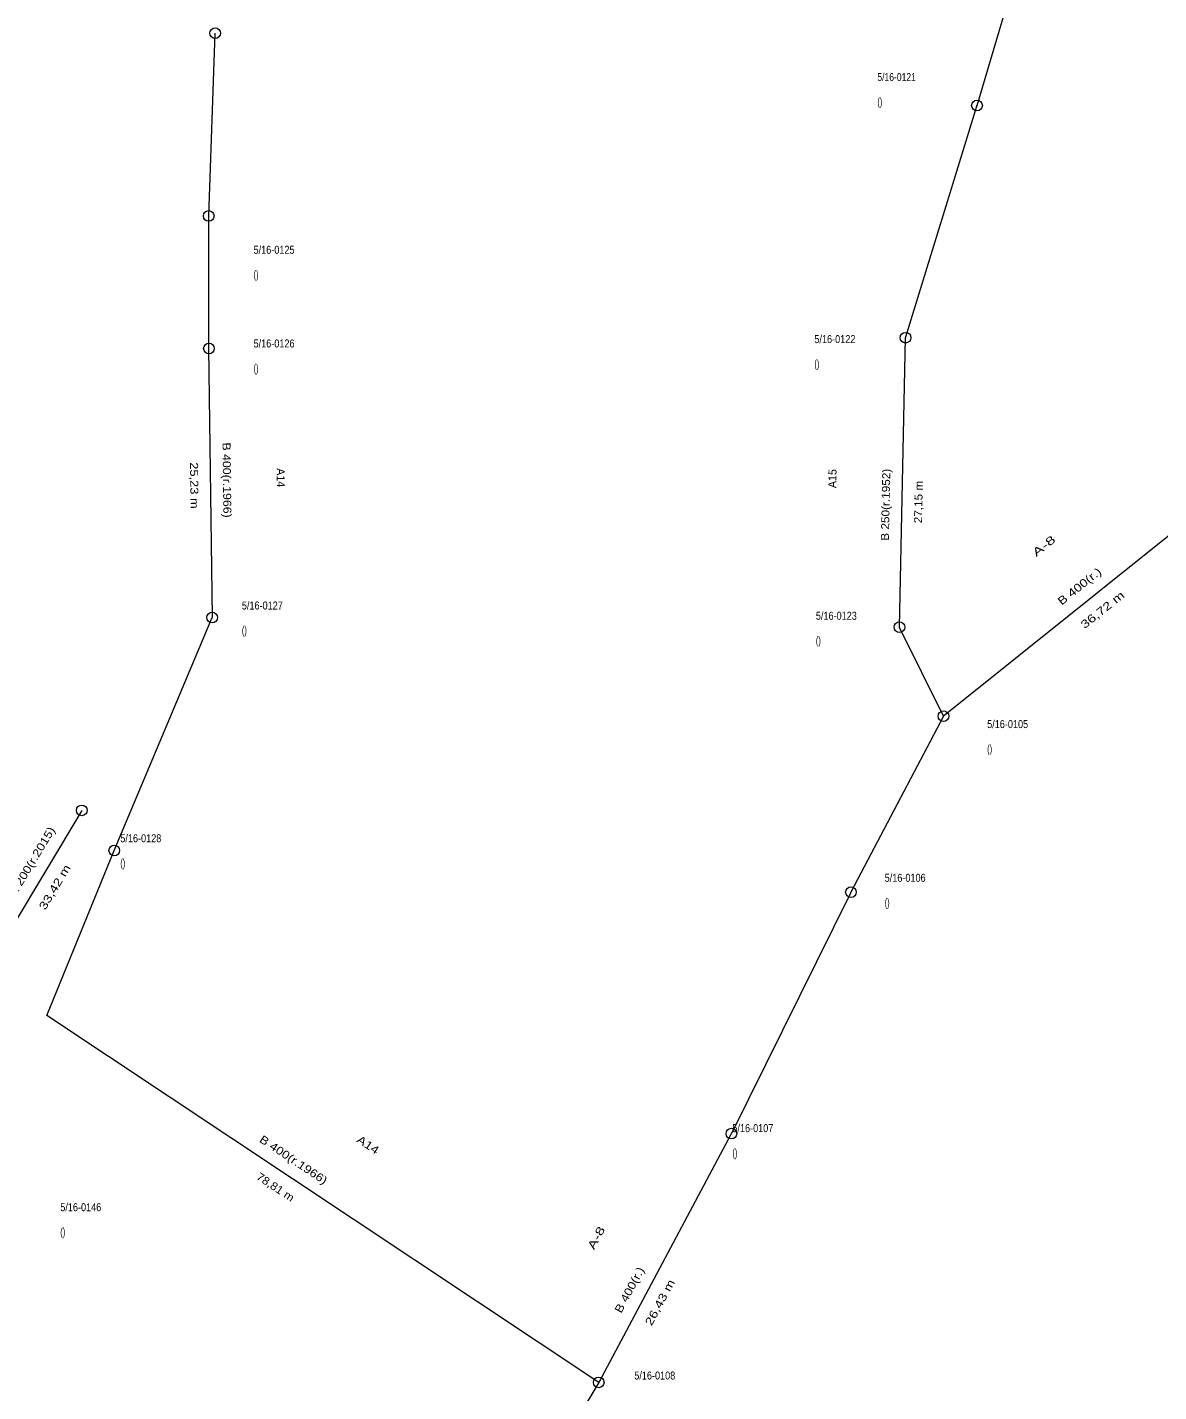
# Model space of a CAD drawing. Extents: x -710854 to -709799, y -1117012 to -1115891.
# Drawn here: x -710384 to -710277.9, y -1116426.2 to -1116298.3 of the extents above; entities that cross this region are included whole.
import ezdxf
from ezdxf.enums import TextEntityAlignment as Align

# ---------------------------------------------------------------- set-up
doc = ezdxf.new("R2010")
doc.units = 0
doc.header["$LTSCALE"] = 0.3
for name, color, linetype, lineweight in [('36', 7, 'Continuous', 13), ('38', 7, 'Continuous', 13), ('44', 7, 'Continuous', 13)]:
    doc.layers.add(name, color=color, linetype=linetype, lineweight=lineweight)
doc.layers.add('48', color=7, linetype='Continuous')

msp = doc.modelspace()

# ---------------------------------------------------------------- linework, layer by layer
at = {"layer": '36'}
msp.add_lwpolyline([(-710378.88, -1116371.72), (-710388.76, -1116388.16), (-710389.13, -1116388.78)], dxfattribs=at)
at = {"layer": '38'}
msp.add_line((-710375.83, -1116375.48), (-710366.654, -1116353.643), dxfattribs=at)
for points in [[(-710294.973, -1116305.64), (-710294.97, -1116305.63), (-710288.78, -1116284.72)], [(-710366.98, -1116315.992), (-710366.98, -1116315.99), (-710366.38, -1116298.86)], [(-710301.668, -1116327.403), (-710301.647, -1116327.335), (-710294.989, -1116305.692), (-710294.973, -1116305.64)], [(-710366.96, -1116328.421), (-710366.96, -1116328.42), (-710366.96, -1116328.387), (-710366.98, -1116315.992)], [(-710302.243, -1116354.545), (-710302.25, -1116354.53), (-710301.67, -1116327.41), (-710301.668, -1116327.403)], [(-710366.654, -1116353.643), (-710366.64, -1116353.61), (-710366.96, -1116328.421)], [(-710269.449, -1116339.945), (-710269.513, -1116339.986), (-710269.55, -1116340.01), (-710298.12, -1116362.88), (-710306.783, -1116379.381)], [(-710298.12, -1116362.88), (-710302.199, -1116354.633), (-710302.243, -1116354.545)], [(-710330.43, -1116425.34), (-710382.14, -1116390.95), (-710375.83, -1116375.48)], [(-710306.783, -1116379.381), (-710306.84, -1116379.49), (-710317.99, -1116402.01), (-710317.995, -1116402.02)], [(-710317.995, -1116402.02), (-710318.009, -1116402.045), (-710330.43, -1116425.34)], [(-710330.43, -1116425.34), (-710338.348, -1116438.576), (-710338.35, -1116438.58), (-710338.376, -1116438.602), (-710356.573, -1116453.802)]]:
    msp.add_lwpolyline(points, dxfattribs=at)
at = {"layer": '44'}
for centre in [(-710366.38, -1116298.86), (-710294.973, -1116305.64), (-710366.98, -1116315.992), (-710301.668, -1116327.403), (-710366.96, -1116328.421), (-710366.654, -1116353.643), (-710302.243, -1116354.545), (-710298.12, -1116362.88), (-710378.88, -1116371.72), (-710375.83, -1116375.48), (-710306.783, -1116379.381), (-710317.995, -1116402.02), (-710330.43, -1116425.34)]:
    msp.add_circle(centre, 0.5, dxfattribs=at)

# ---------------------------------------------------------------- texts
at = {"layer": '48'}
for s, width, p in [('5/16-0121', 0.8, (-710304.313, -1116303.343)), ('()', 0.7, (-710304.313, -1116305.653)), ('5/16-0125', 0.85, (-710362.777, -1116319.537)), ('()', 0.7, (-710362.777, -1116321.847)), ('5/16-0126', 0.85, (-710362.777, -1116328.32)), ('5/16-0122', 0.85, (-710310.214, -1116327.909)), ('()', 0.7, (-710362.777, -1116330.63)), ('()', 0.7, (-710310.214, -1116330.219)), ('5/16-0127', 0.85, (-710363.875, -1116352.886)), ('5/16-0123', 0.85, (-710310.077, -1116353.847)), ('()', 0.7, (-710363.875, -1116355.196)), ('()', 0.7, (-710310.077, -1116356.157)), ('5/16-0105', 0.85, (-710294.02, -1116364.003)), ('()', 0.7, (-710294.02, -1116366.313)), ('5/16-0128', 0.85, (-710375.266, -1116374.707)), ('()', 0.7, (-710375.266, -1116377.017)), ('5/16-0106', 0.85, (-710303.627, -1116378.413)), ('()', 0.7, (-710303.627, -1116380.723)), ('5/16-0107', 0.85, (-710317.9, -1116401.881)), ('()', 0.7, (-710317.9, -1116404.191)), ('5/16-0146', 0.85, (-710380.893, -1116409.292)), ('()', 0.7, (-710380.893, -1116411.602)), ('5/16-0108', 0.85, (-710327.095, -1116425.074))]:
    msp.add_text(s, height=0.75, dxfattribs=dict(at, width=width)).set_placement(p)
for s, rotation, width, p in [('B 400(r.1966)', 270.73, 1.15, (-710365.644, -1116340.7587)), ('25,23 m', 270.73, 1.2, (-710368.7073, -1116341.2637)), ('B 250(r.1952)', 88.77, 1.1, (-710303.1647, -1116343.0695)), ('27,15 m', 88.77, 1.1, (-710300.0887, -1116342.819)), ('A-8', 38.68, 1.55, (-710288.4774, -1116347.2195)), ('B 400(r.)', 38.68, 1.25, (-710285.1339, -1116350.9998)), ('36,72 m', 38.68, 1.35, (-710282.9779, -1116353.206)), ('PVC-K 200(r.2015)', 59, 1.2, (-710383.9691, -1116377.9366)), ('33,42 m', 59, 1.3, (-710381.091, -1116379.1056)), ('B 400(r.1966)', 326.37, 1.2, (-710359.2407, -1116404.7862)), ('A14', 326.37, 1.25, (-710352.2557, -1116403.3792)), ('78,81 m', 326.37, 1.1, (-710360.9322, -1116407.349)), ('A-8', 61.93, 1.45, (-710330.3296, -1116411.973)), ('B 400(r.)', 61.93, 1.2, (-710327.2175, -1116416.8475)), ('26,43 m', 61.93, 1.3, (-710324.365, -1116418.0235))]:
    msp.add_text(s, height=0.75, rotation=rotation, dxfattribs=dict(at, width=width)).set_placement(p, align=Align.CENTER)
for s, rotation, p in [('A14', 270.73, (-710360.605, -1116340.5337)), ('A15', 88.77, (-710308.1535, -1116340.617))]:
    msp.add_text(s, height=0.75, rotation=rotation, dxfattribs=at).set_placement(p, align=Align.CENTER)

doc.saveas('drawing.dxf')
